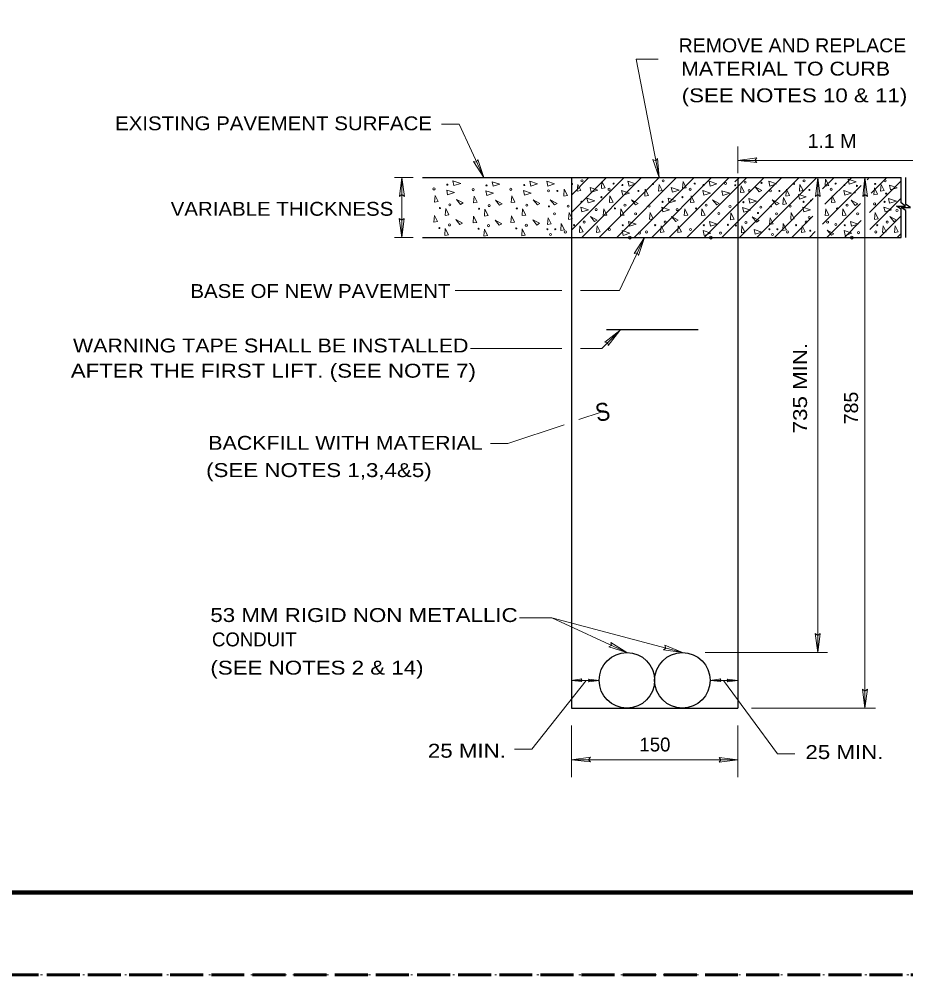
# Model space of a CAD drawing. Extents: x 312583 to 312854, y 144419 to 144597.
# Drawn here: x 312621.2 to 312669.7, y 144418.6 to 144470.8 of the extents above; entities that cross this region are included whole.
import ezdxf
from ezdxf.enums import TextEntityAlignment as Align

# ---------------------------------------------------------------- set-up
doc = ezdxf.new("R2010")
doc.units = 0
doc.header["$LTSCALE"] = 0.3
doc.header["$PDMODE"] = 32
doc.header["$PDSIZE"] = 0.15
doc.linetypes.add('DOTTED', pattern=[1.5, 0.3, -1.2])
doc.linetypes.add('LONG_DASHED', pattern=[7.5, 6, -1.5])
for name, color, linetype, lineweight in [('1', 7, 'Continuous', 13), ('62', 7, 'DOTTED', 13), ('63', 7, 'LONG_DASHED', 60)]:
    doc.layers.add(name, color=color, linetype=linetype, lineweight=lineweight)

msp = doc.modelspace()

# ---------------------------------------------------------------- linework, layer by layer
at = {"layer": '1'}
for p, q in [((312645.2426, 144465.0856), (312644.2919, 144465.0856)), ((312645.2426, 144465.0856), (312646.5996, 144462.1799)), ((312660.4992, 144463.8819), (312660.4992, 144462.4099)), ((312660.4992, 144463.1153), (312671.4549, 144463.1153)), ((312642.7279, 144462.1799), (312641.7082, 144462.1799)), ((312642.1146, 144462.1799), (312642.1146, 144458.9063)), ((312651.3912, 144459.3049), (312654.2662, 144462.1799)), ((312651.3912, 144460.2633), (312653.3079, 144462.1799)), ((312651.3912, 144461.2216), (312652.3496, 144462.1799)), ((312651.9509, 144458.9063), (312655.2246, 144462.1799)), ((312652.9092, 144458.9063), (312656.1829, 144462.1799)), ((312653.8676, 144458.9063), (312657.1412, 144462.1799)), ((312654.8259, 144458.9063), (312658.0996, 144462.1799)), ((312655.7842, 144458.9063), (312659.0579, 144462.1799)), ((312656.7426, 144458.9063), (312660.0162, 144462.1799)), ((312657.7009, 144458.9063), (312660.9746, 144462.1799)), ((312658.6592, 144458.9063), (312661.9329, 144462.1799)), ((312659.6176, 144458.9063), (312662.8912, 144462.1799)), ((312660.3229, 144461.9346), (312660.5759, 144462.1799)), ((312660.5759, 144458.9063), (312663.8496, 144462.1799)), ((312661.5342, 144458.9063), (312664.8079, 144462.1799)), ((312664.8616, 144462.1799), (312664.8616, 144436.2053)), ((312665.1299, 144461.5513), (312665.7662, 144462.1799)), ((312665.2526, 144460.7156), (312666.7246, 144462.1799)), ((312667.4452, 144462.1799), (312667.4452, 144433.1693)), ((312667.5602, 144462.0573), (312667.6829, 144462.1799)), ((312667.6906, 144460.2709), (312669.4156, 144462.0036)), ((312667.7826, 144461.3213), (312668.6412, 144462.1799)), ((312665.1222, 144459.6193), (312667.2382, 144461.7353)), ((312662.4926, 144458.9063), (312664.6086, 144461.0223)), ((312667.7059, 144459.3356), (312669.4156, 144461.0453)), ((312665.3676, 144458.9063), (312667.2076, 144460.7539)), ((312663.4509, 144458.9063), (312664.6009, 144460.0563)), ((312666.3259, 144458.9063), (312667.2382, 144459.8186)), ((312668.2426, 144458.9063), (312669.4156, 144460.0869)), ((312642.7279, 144458.9063), (312641.7082, 144458.9063)), ((312654.0286, 144456.0006), (312655.3856, 144458.9063)), ((312664.4092, 144458.9063), (312664.7236, 144459.2206)), ((312669.2009, 144458.9063), (312669.4002, 144459.1056)), ((312650.8699, 144456.0006), (312645.0279, 144456.0006)), ((312654.0286, 144456.0006), (312651.8896, 144456.0006)), ((312653.0626, 144452.8343), (312654.0976, 144453.8693)), ((312650.8699, 144452.8343), (312645.8789, 144452.8343)), ((312653.0626, 144452.8343), (312651.8896, 144452.8343)), ((312651.7976, 144448.9396), (312653.0166, 144449.3536)), ((312647.9182, 144447.6286), (312650.9849, 144448.6636)), ((312647.9182, 144447.6286), (312646.9599, 144447.6286)), ((312650.3256, 144438.1066), (312648.5469, 144438.1066)), ((312650.3256, 144438.1066), (312654.4272, 144436.2053)), ((312650.3256, 144438.1066), (312657.4632, 144436.2053)), ((312658.6976, 144436.2053), (312665.3906, 144436.2053)), ((312649.2216, 144430.9306), (312652.1962, 144434.6719)), ((312652.9092, 144434.6873), (312651.3912, 144434.6873)), ((312660.4992, 144434.6873), (312658.9812, 144434.6873)), ((312659.7019, 144434.6719), (312662.6536, 144430.6699)), ((312661.2429, 144433.1693), (312668.0126, 144433.1693)), ((312651.3912, 144432.2109), (312651.3912, 144429.3896)), ((312660.4992, 144432.2109), (312660.4992, 144429.3896)), ((312649.2216, 144430.9306), (312648.2709, 144430.9306)), ((312663.6119, 144430.6699), (312662.6536, 144430.6699)), ((312660.4992, 144430.3479), (312651.3912, 144430.3479))]:
    msp.add_line(p, q, dxfattribs=at)
at = {"layer": '1', "lineweight": 25}
for p, q in [((312643.2416, 144462.1799), (312669.4156, 144462.1799)), ((312646.5996, 144462.1799), (312661.4576, 144462.1799)), ((312651.3912, 144462.1799), (312651.3912, 144433.1693)), ((312660.4992, 144462.1799), (312660.4992, 144458.9063)), ((312643.2416, 144458.9063), (312649.8732, 144458.9063)), ((312649.8732, 144458.9063), (312669.4156, 144458.9063)), ((312660.4992, 144458.9063), (312660.4992, 144433.1693)), ((312653.3156, 144453.8693), (312658.3142, 144453.8693)), ((312651.3912, 144433.1693), (312660.4992, 144433.1693))]:
    msp.add_line(p, q, dxfattribs=at)
at = {"layer": '1', "lineweight": 158}
msp.add_line((312616.5, 144423.0846), (312849, 144423.0846), dxfattribs=at)
at = {"layer": '1'}
for points in [[(312656.1292, 144468.6429), (312654.9332, 144468.6429), (312656.1829, 144462.1799)], [(312653.0319, 144461.5896), (312653.0626, 144461.9576), (312653.2312, 144461.6126), (312653.0319, 144461.5819)], [(312657.4709, 144461.5896), (312657.5016, 144461.9576), (312657.6702, 144461.6126), (312657.4709, 144461.5819)], [(312665.2679, 144461.7199), (312665.2909, 144462.0803), (312665.4596, 144461.7429), (312665.2679, 144461.7123)], [(312650.9696, 144461.1679), (312651.0002, 144461.5359), (312651.1689, 144461.1909), (312650.9696, 144461.1603)], [(312651.7132, 144461.4363), (312651.7439, 144461.8043), (312651.9126, 144461.4593), (312651.7132, 144461.4286)], [(312655.4086, 144461.1679), (312655.4316, 144461.5359), (312655.6002, 144461.1909), (312655.4086, 144461.1603)], [(312656.1522, 144461.4363), (312656.1829, 144461.8043), (312656.3516, 144461.4593), (312656.1522, 144461.4286)], [(312660.6449, 144461.3596), (312660.6756, 144461.7276), (312660.8442, 144461.3826), (312660.6449, 144461.3519)], [(312663.1136, 144461.1679), (312663.1442, 144461.5359), (312663.3129, 144461.1909), (312663.1136, 144461.1603)], [(312663.8572, 144461.4363), (312663.8879, 144461.8043), (312664.0566, 144461.4593), (312663.8572, 144461.4286)], [(312667.9359, 144461.2446), (312667.9589, 144461.6049), (312668.1352, 144461.2676), (312667.9359, 144461.2369)], [(312668.2962, 144461.4363), (312668.3269, 144461.8043), (312668.4956, 144461.4593), (312668.2962, 144461.4286)], [(312643.9009, 144460.8306), (312643.9316, 144461.1986), (312644.1002, 144460.8613), (312643.9009, 144460.8229)], [(312646.0399, 144460.7923), (312646.0706, 144461.1603), (312646.2392, 144460.8229), (312646.0399, 144460.7846)], [(312648.1022, 144460.8153), (312648.1329, 144461.1756), (312648.3016, 144460.8383), (312648.1099, 144460.8076)], [(312653.4766, 144460.8153), (312653.4996, 144461.1756), (312653.6759, 144460.8383), (312653.4766, 144460.8076)], [(312657.9079, 144460.8153), (312657.9386, 144461.1756), (312658.1072, 144460.8383), (312657.9079, 144460.8076)], [(312662.9602, 144460.7079), (312662.9909, 144461.0759), (312663.1596, 144460.7386), (312662.9679, 144460.7003)], [(312665.6206, 144460.8153), (312665.6436, 144461.1756), (312665.8199, 144460.8383), (312665.6206, 144460.8076)], [(312644.4912, 144460.1176), (312644.5219, 144460.4856), (312644.6906, 144460.1406), (312644.4912, 144460.1099)], [(312646.6302, 144460.0793), (312646.6609, 144460.4473), (312646.8296, 144460.1023), (312646.6379, 144460.0716)], [(312658.4982, 144460.0946), (312658.5289, 144460.4626), (312658.6976, 144460.1253), (312658.5059, 144460.0946)], [(312648.0792, 144459.7189), (312648.1099, 144460.0869), (312648.2786, 144459.7419), (312648.0792, 144459.7113)], [(312651.2379, 144459.8953), (312651.2686, 144460.2633), (312651.4372, 144459.9183), (312651.2379, 144459.8876)], [(312655.6692, 144459.8953), (312655.6999, 144460.2633), (312655.8686, 144459.9183), (312655.6769, 144459.8876)], [(312663.3819, 144459.8953), (312663.4126, 144460.2633), (312663.5812, 144459.9183), (312663.3819, 144459.8876)], [(312667.9666, 144459.8953), (312667.9972, 144460.2633), (312668.1659, 144459.9183), (312667.9666, 144459.8876)], [(312644.4682, 144459.0213), (312644.4912, 144459.3893), (312644.6599, 144459.0443), (312644.4682, 144459.0136)], [(312646.6072, 144458.9829), (312646.6379, 144459.3509), (312646.8066, 144459.0059), (312646.6072, 144458.9753)], [(312652.7636, 144459.1746), (312652.7942, 144459.5426), (312652.9629, 144459.2053), (312652.7712, 144459.1746)], [(312660.6832, 144459.1593), (312660.7139, 144459.5273), (312660.8826, 144459.1899), (312660.6832, 144459.1516)]]:
    msp.add_lwpolyline(points, dxfattribs=at)
for points in [[(312646.2776, 144463.1689), (312646.5996, 144462.1799), (312646.0322, 144463.0616), (312646.2009, 144463.0233)], [(312656.1062, 144463.2226), (312656.1829, 144462.1799), (312655.8456, 144463.1689), (312655.9989, 144463.0923)], [(312661.5342, 144462.9926), (312660.4992, 144463.1153), (312661.5342, 144463.2533), (312661.4269, 144463.1153)], [(312641.9919, 144461.1449), (312642.1146, 144462.1799), (312642.2526, 144461.1449), (312642.1146, 144461.2446)], [(312644.9052, 144461.9883), (312644.9666, 144461.7353), (312645.3346, 144461.8503)], [(312647.0519, 144461.9499), (312647.1056, 144461.6969), (312647.4736, 144461.8119)], [(312649.1142, 144461.9729), (312649.1679, 144461.7123), (312649.5359, 144461.8273)], [(312650.0496, 144461.9729), (312650.1032, 144461.7123), (312650.4712, 144461.8273)], [(312654.4809, 144461.9729), (312654.5422, 144461.7123), (312654.9026, 144461.8273)], [(312658.9199, 144461.9729), (312658.9736, 144461.7123), (312659.3416, 144461.8273)], [(312662.1936, 144461.9729), (312662.2472, 144461.7123), (312662.6152, 144461.8273)], [(312664.7389, 144461.1449), (312664.8616, 144462.1799), (312664.9996, 144461.1449), (312664.8616, 144461.2446)], [(312666.5329, 144462.0803), (312666.5866, 144461.8196), (312666.9546, 144461.9346)], [(312667.3226, 144461.1449), (312667.4452, 144462.1799), (312667.5832, 144461.1449), (312667.4452, 144461.2446)], [(312644.5679, 144461.4899), (312644.6216, 144461.2369), (312644.9896, 144461.3519)], [(312646.7069, 144461.4516), (312646.7606, 144461.1986), (312647.1286, 144461.3136)], [(312648.7692, 144461.4746), (312648.8306, 144461.2139), (312649.1909, 144461.3289)], [(312652.4186, 144461.6279), (312652.4722, 144461.3749), (312652.8402, 144461.4823)], [(312654.1359, 144461.4746), (312654.1972, 144461.2139), (312654.5652, 144461.3289)], [(312656.8499, 144461.6279), (312656.9112, 144461.3749), (312657.2792, 144461.4823)], [(312658.5749, 144461.4746), (312658.6286, 144461.2139), (312658.9966, 144461.3289)], [(312659.6252, 144461.4516), (312659.6789, 144461.1986), (312660.0469, 144461.3136)], [(312661.8026, 144461.4746), (312661.4346, 144461.6739), (312661.6646, 144461.3903)], [(312666.2799, 144461.4746), (312666.3412, 144461.2139), (312666.7092, 144461.3289)], [(312668.7869, 144461.7506), (312668.8406, 144461.4976), (312669.2086, 144461.6049)], [(312645.4649, 144460.7846), (312645.0969, 144460.9839), (312645.3192, 144460.7003)], [(312647.6039, 144460.7463), (312647.2359, 144460.9456), (312647.4659, 144460.6619)], [(312649.6662, 144460.7616), (312649.2982, 144460.9609), (312649.5282, 144460.6773)], [(312650.6016, 144460.7616), (312650.2336, 144460.9609), (312650.4636, 144460.6773)], [(312652.2422, 144461.0529), (312652.3036, 144460.7999), (312652.6716, 144460.9073)], [(312655.0406, 144460.7616), (312654.6726, 144460.9609), (312654.8949, 144460.6773)], [(312656.6812, 144461.0529), (312656.7349, 144460.7999), (312657.1029, 144460.9073)], [(312659.4719, 144460.7616), (312659.1039, 144460.9609), (312659.3339, 144460.6773)], [(312661.0972, 144461.0299), (312661.1509, 144460.7769), (312661.5189, 144460.8919)], [(312662.7456, 144460.7616), (312662.3776, 144460.9609), (312662.6076, 144460.6773)], [(312663.8036, 144461.2523), (312663.8572, 144460.9993), (312664.2252, 144461.1143)], [(312667.0542, 144460.7309), (312666.6862, 144460.9303), (312666.9086, 144460.6466)], [(312668.7332, 144461.0376), (312668.7946, 144460.7769), (312669.1626, 144460.8919)], [(312648.7002, 144460.0946), (312648.7232, 144460.4626), (312648.8996, 144460.1253)], [(312651.9049, 144460.5546), (312651.9586, 144460.3016), (312652.3266, 144460.4089)], [(312653.1316, 144460.0946), (312653.1622, 144460.4626), (312653.3309, 144460.1253)], [(312654.0669, 144460.0946), (312654.0976, 144460.4626), (312654.2662, 144460.1253)], [(312656.3362, 144460.5546), (312656.3976, 144460.3016), (312656.7579, 144460.4089)], [(312657.5629, 144460.0946), (312657.5936, 144460.4626), (312657.7622, 144460.1253)], [(312660.7522, 144460.5316), (312660.8136, 144460.2786), (312661.1816, 144460.3936)], [(312664.0489, 144460.5546), (312664.1026, 144460.3016), (312664.4706, 144460.4089)], [(312665.2756, 144460.0946), (312665.3062, 144460.4626), (312665.4749, 144460.1253)], [(312666.2109, 144460.0946), (312666.2416, 144460.4626), (312666.4102, 144460.1253)], [(312668.4802, 144460.5546), (312668.5416, 144460.3016), (312668.9019, 144460.4089)], [(312642.2449, 144459.9413), (312642.1146, 144458.9063), (312641.9766, 144459.9413), (312642.1146, 144459.8416)], [(312643.8702, 144459.7343), (312643.9009, 144460.1023), (312644.0696, 144459.7649)], [(312645.4342, 144459.6883), (312645.0662, 144459.8876), (312645.2962, 144459.6039)], [(312646.0169, 144459.6959), (312646.0399, 144460.0639), (312646.2162, 144459.7266)], [(312647.5809, 144459.6499), (312647.2129, 144459.8493), (312647.4352, 144459.5656)], [(312649.6432, 144459.6729), (312649.2752, 144459.8646), (312649.4976, 144459.5809)], [(312650.0879, 144459.6116), (312650.1109, 144459.9796), (312650.2796, 144459.6423)], [(312652.8019, 144459.8493), (312652.4339, 144460.0409), (312652.6562, 144459.7649)], [(312654.5039, 144459.7726), (312654.5576, 144459.5119), (312654.9256, 144459.6269)], [(312657.2332, 144459.8493), (312656.8652, 144460.0409), (312657.0952, 144459.7649)], [(312658.9352, 144459.7726), (312658.9966, 144459.5119), (312659.3569, 144459.6269)], [(312660.0929, 144459.8723), (312660.1159, 144460.2403), (312660.2846, 144459.9029)], [(312661.6492, 144459.8263), (312661.2812, 144460.0256), (312661.5112, 144459.7419)], [(312662.2319, 144459.6116), (312662.2549, 144459.9796), (312662.4236, 144459.6423)], [(312666.6479, 144459.7726), (312666.7016, 144459.5119), (312667.0696, 144459.6269)], [(312669.1702, 144459.8493), (312668.8022, 144460.0409), (312669.0246, 144459.7649)], [(312648.6696, 144458.9983), (312648.7002, 144459.3663), (312648.8689, 144459.0289)], [(312650.8086, 144459.2896), (312650.8316, 144459.6576), (312651.0079, 144459.3203)], [(312651.8282, 144459.1746), (312651.8589, 144459.5426), (312652.0276, 144459.2053)], [(312654.1589, 144459.2743), (312654.2126, 144459.0136), (312654.5806, 144459.1286)], [(312656.2672, 144459.1746), (312656.2902, 144459.5426), (312656.4666, 144459.2053)], [(312657.2026, 144459.1746), (312657.2332, 144459.5426), (312657.4019, 144459.2053)], [(312658.5902, 144459.2743), (312658.6516, 144459.0136), (312659.0196, 144459.1286)], [(312661.3809, 144459.3279), (312661.4422, 144459.0749), (312661.8102, 144459.1899)], [(312662.9526, 144459.2896), (312662.9756, 144459.6576), (312663.1519, 144459.3203)], [(312663.9722, 144459.1746), (312664.0029, 144459.5426), (312664.1716, 144459.2053)], [(312665.7432, 144459.1056), (312665.3752, 144459.3049), (312665.6052, 144459.0213)], [(312666.3029, 144459.2743), (312666.3566, 144459.0136), (312666.7246, 144459.1286)], [(312668.4112, 144459.1746), (312668.4342, 144459.5426), (312668.6106, 144459.2053)], [(312669.0629, 144459.1746), (312669.0936, 144459.5426), (312669.2622, 144459.2053)], [(312655.0636, 144457.9173), (312655.3856, 144458.9063), (312654.8182, 144458.0246), (312654.9869, 144458.0629)], [(312653.3999, 144452.9953), (312654.0439, 144453.8156), (312653.2159, 144453.1793), (312653.3846, 144453.1563)], [(312653.4306, 144436.5273), (312654.4272, 144436.2053), (312653.5456, 144436.7649), (312653.5762, 144436.5963)], [(312664.9919, 144437.2403), (312664.8616, 144436.2053), (312664.7236, 144437.2403), (312664.8616, 144437.1406)], [(312656.4282, 144436.3586), (312657.4632, 144436.2053), (312656.4972, 144436.6116), (312656.5586, 144436.4506)], [(312651.9662, 144434.6183), (312651.3912, 144434.6873), (312651.9662, 144434.7639), (312651.9126, 144434.6873)], [(312652.3266, 144434.7563), (312652.9092, 144434.6873), (312652.3266, 144434.6106), (312652.3802, 144434.6873)], [(312659.5562, 144434.6183), (312658.9812, 144434.6873), (312659.5562, 144434.7639), (312659.5026, 144434.6873)], [(312659.9166, 144434.7563), (312660.4992, 144434.6873), (312659.9166, 144434.6106), (312659.9702, 144434.6873)], [(312667.5756, 144434.2043), (312667.4452, 144433.1693), (312667.3072, 144434.2043), (312667.4452, 144434.1046)], [(312652.4262, 144430.2253), (312651.3912, 144430.3479), (312652.4262, 144430.4859), (312652.3189, 144430.3479)], [(312659.4642, 144430.4783), (312660.4992, 144430.3479), (312659.4642, 144430.2099), (312659.5639, 144430.3479)]]:
    msp.add_lwpolyline(points, close=True, dxfattribs=at)
at = {"layer": '1', "lineweight": 25}
for points in [[(312669.4156, 144458.9063), (312669.4156, 144460.4549), (312669.1702, 144460.6159), (312669.6686, 144460.6159), (312669.4156, 144460.7846), (312669.4156, 144462.1799)], [(312669.6839, 144458.9063), (312669.6839, 144460.3783), (312669.4309, 144460.5393), (312669.9369, 144460.5393), (312669.6839, 144460.7079), (312669.6839, 144462.1799)]]:
    msp.add_lwpolyline(points, dxfattribs=at)
at = {"layer": '1'}
for centre, radius in [((312651.4219, 144461.8292), 0.0288), ((312651.9691, 144461.9998), 0.0565), ((312653.697, 144461.8483), 0.0288), ((312655.8571, 144461.8292), 0.0288), ((312656.4043, 144461.9998), 0.0565), ((312658.1322, 144461.8483), 0.0288), ((312659.815, 144461.8579), 0.0565), ((312660.8969, 144461.9231), 0.0565), ((312661.7844, 144461.8867), 0.0288), ((312663.5659, 144461.8292), 0.0288), ((312664.1131, 144461.9998), 0.0565), ((312665.841, 144461.8483), 0.0288), ((312668.0011, 144461.8292), 0.0288), ((312668.5483, 144461.9998), 0.0565), ((312643.8731, 144461.5522), 0.0565), ((312644.6034, 144461.7861), 0.0288), ((312646.015, 144461.5139), 0.0565), ((312646.7452, 144461.7477), 0.0288), ((312648.0792, 144461.5331), 0.0565), ((312648.8095, 144461.7669), 0.0288), ((312650.1358, 144461.4497), 0.0565), ((312650.6198, 144461.4468), 0.0288), ((312653.4478, 144461.5331), 0.0565), ((312654.1781, 144461.7669), 0.0288), ((312655.0549, 144461.4468), 0.0288), ((312657.883, 144461.5331), 0.0565), ((312658.6132, 144461.7669), 0.0288), ((312660.3497, 144461.7525), 0.0288), ((312661.1068, 144461.4641), 0.0565), ((312662.2798, 144461.4497), 0.0565), ((312662.7638, 144461.4468), 0.0288), ((312664.4073, 144461.4976), 0.0288), ((312665.5918, 144461.5331), 0.0565), ((312666.3221, 144461.7669), 0.0288), ((312666.8884, 144461.3606), 0.0288), ((312667.0082, 144461.7228), 0.0288), ((312668.6039, 144461.2973), 0.0288), ((312651.9413, 144460.8488), 0.0288), ((312653.0281, 144461.1028), 0.0288), ((312656.3765, 144460.8488), 0.0288), ((312657.4632, 144461.1028), 0.0288), ((312660.7934, 144460.8296), 0.0288), ((312664.0853, 144460.8488), 0.0288), ((312664.4926, 144460.9188), 0.0288), ((312668.5205, 144460.8488), 0.0288), ((312644.198, 144460.5096), 0.0288), ((312644.7452, 144460.6801), 0.0565), ((312646.3399, 144460.4712), 0.0288), ((312646.8871, 144460.6418), 0.0565), ((312648.4041, 144460.4904), 0.0288), ((312648.9513, 144460.661), 0.0565), ((312650.1569, 144460.5996), 0.0288), ((312651.2111, 144460.615), 0.0565), ((312652.7406, 144460.4233), 0.0565), ((312653.7727, 144460.4904), 0.0288), ((312654.3199, 144460.661), 0.0565), ((312655.6462, 144460.615), 0.0565), ((312657.1757, 144460.4233), 0.0565), ((312658.2079, 144460.4904), 0.0288), ((312658.7551, 144460.661), 0.0565), ((312660.0632, 144460.5958), 0.0565), ((312661.7451, 144460.5575), 0.0565), ((312662.3009, 144460.5996), 0.0288), ((312663.3551, 144460.615), 0.0565), ((312665.9167, 144460.4904), 0.0288), ((312666.4639, 144460.661), 0.0565), ((312667.9723, 144460.7329), 0.0565), ((312669.1961, 144460.3706), 0.0565), ((312650.4655, 144460.1943), 0.0565), ((312652.0832, 144459.7429), 0.0565), ((312654.9007, 144460.1943), 0.0565), ((312656.5183, 144459.7429), 0.0565), ((312659.4518, 144460.2134), 0.0565), ((312660.9353, 144459.7237), 0.0565), ((312661.5965, 144460.2364), 0.0288), ((312662.6095, 144460.1943), 0.0565), ((312664.2271, 144459.7429), 0.0565), ((312664.3949, 144459.9901), 0.0565), ((312665.4021, 144459.7333), 0.0565), ((312667.0446, 144460.1943), 0.0565), ((312668.6623, 144459.7429), 0.0565), ((312644.1712, 144459.4142), 0.0288), ((312644.7184, 144459.5848), 0.0565), ((312646.313, 144459.3759), 0.0288), ((312646.8602, 144459.5464), 0.0565), ((312648.3773, 144459.395), 0.0288), ((312648.9245, 144459.5656), 0.0565), ((312650.0774, 144459.3481), 0.0288), ((312650.5096, 144459.3481), 0.0288), ((312651.0587, 144459.1995), 0.0565), ((312651.5359, 144459.5723), 0.0288), ((312653.467, 144459.3327), 0.0565), ((312654.1972, 144459.5666), 0.0288), ((312655.4939, 144459.1995), 0.0565), ((312655.9711, 144459.5723), 0.0288), ((312657.9021, 144459.3327), 0.0565), ((312658.6324, 144459.5666), 0.0288), ((312659.9492, 144459.5915), 0.0288), ((312660.3881, 144459.5531), 0.0288), ((312662.2214, 144459.3481), 0.0288), ((312662.6536, 144459.3481), 0.0288), ((312663.2027, 144459.1995), 0.0565), ((312663.6799, 144459.5723), 0.0288), ((312664.4543, 144459.2704), 0.0288), ((312665.8467, 144459.6106), 0.0565), ((312666.3412, 144459.5666), 0.0288), ((312668.0442, 144459.1995), 0.0565), ((312668.1151, 144459.5723), 0.0288), ((312650.2479, 144459.0586), 0.0565), ((312655.1124, 144459.142), 0.0565), ((312659.5476, 144459.142), 0.0565), ((312662.3919, 144459.0586), 0.0565), ((312667.0954, 144459.1631), 0.0565)]:
    msp.add_circle(centre, radius, dxfattribs=at)
at = {"layer": '1', "lineweight": 25}
for centre in [(312654.4234, 144434.6892), (312657.4594, 144434.6892)]:
    msp.add_circle(centre, 1.518, dxfattribs=at)
at = {"layer": '1'}
for p in [(312654.5806, 144458.8909), (312659.0119, 144458.8909), (312666.7246, 144458.8909)]:
    msp.add_point(p, dxfattribs=at)
at = {"layer": '62'}
msp.add_lwpolyline([(312601.2, 144418.5846), (312853.5, 144418.5846), (312853.5, 144596.7846)], dxfattribs=at)
at = {"layer": '63'}
msp.add_line((312851.75, 144418.5846), (312583.526, 144418.5846), dxfattribs=at)

# ---------------------------------------------------------------- texts
at = {"layer": '1'}
for s, width, p in [('REMOVE AND REPLACE', 1.05, (312657.2518, 144469.0226)), ('MATERIAL TO CURB', 1.15, (312657.3882, 144467.7498)), ('(SEE NOTES 10 & 11)', 1.2, (312657.4216, 144466.2909)), ('EXISTING PAVEMENT SURFACE', 1.1, (312626.433, 144464.7612)), ('1.1 M', 1.05, (312664.3098, 144463.7923)), ('VARIABLE THICKNESS', 1.1, (312629.4742, 144460.0853)), ('BASE OF NEW PAVEMENT', 1.1, (312630.5502, 144455.5919)), ('WARNING TAPE SHALL BE INSTALLED', 1.15, (312624.1318, 144452.6119)), ('AFTER THE FIRST LIFT. (SEE NOTE 7)', 1.2, (312624.0106, 144451.2342)), ('BACKFILL WITH MATERIAL', 1.15, (312631.5329, 144447.2913)), ('(SEE NOTES 1,3,4&5)', 1.2, (312631.4113, 144445.8008)), ('53 MM RIGID NON METALLIC', 1.2, (312631.6433, 144437.8768)), ('(SEE NOTES 2 & 14)', 1.2, (312631.6456, 144435.0009)), ('25 MIN.', 1.2, (312643.5388, 144430.4584)), ('25 MIN.', 1.2, (312664.1882, 144430.3841))]:
    msp.add_text(s, height=0.76, dxfattribs=dict(at, width=width)).set_placement(p)
for s, width, p in [('735 MIN.', 1.2, (312664.2749, 144448.192)), ('785', 1.05, (312667.064, 144448.6856))]:
    msp.add_text(s, height=0.76, rotation=90, dxfattribs=dict(at, width=width)).set_placement(p)
at = {"layer": '1', "width": 0.9}
msp.add_text('S', height=0.9804, rotation=10, dxfattribs=at).set_placement((312653.1817, 144448.8839), align=Align.CENTER)
at = {"layer": '1'}
for s, p in [('CONDUIT', (312631.7314, 144436.5451)), ('150', (312655.1082, 144430.7979))]:
    msp.add_text(s, height=0.76, dxfattribs=at).set_placement(p)

doc.saveas('drawing.dxf')
